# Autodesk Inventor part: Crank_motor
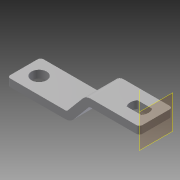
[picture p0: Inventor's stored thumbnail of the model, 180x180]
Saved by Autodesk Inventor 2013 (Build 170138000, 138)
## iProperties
Created: 2006-03
Part Number: Crank_motor
Document SubType Name: Modeling
Designer: debonom
Material: Stainless Steel, 440C
Mass: 73.5464 g
Surface Area: 52.6545 cm^2
Volume: 9.48986 cm^3
Density: 7.75 g/cm^3
Author: debonom
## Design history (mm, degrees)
sketch "Sketch1"
  geometry: L1 (0, 0)-(-34.15, 0); L2 (0, 0)-(12.586, -15); L3 (12.586, -15)-(53.05, -15)
  constraints: 6 end point, 1 horizontal, 1 parallel
  dimensions: "d0" = 130 deg angle of L2 L1; "d1" = 87.2 horizontal distance of L3.end L1.end; "d2" = 34.15 distance of L1.start L1.end; "d3" = 15 distance between parallel lines of L3 L1
workplane "Work Plane1"
sketch "Sketch2"
  geometry: L1 (-11, 2.5)-(11, 2.5); L2 (11, 2.5)-(11, -2.5); L3 (11, -2.5)-(-11, -2.5); L4 (-11, -2.5)-(-11, 2.5); L5 (-11, 2.5)-(11, -2.5); 2 further points
  constraints: 10 end point, 2 parallel, 1 coincident, 1 horizontal, 1 midpoint, 1 perpendicular
  dimensions: "d4" = 22 distance of L1.start L1.end; "d5" = 5 distance of L3.end L1.start
sweep "Sweep1" sketch "Sketch2" dims "d6" = 0
fillet "Fillet1" dims "d7" = 7
fillet "Fillet2" dims "d8" = 2
sketch "Sketch4"
  geometry: L1 (-104.64, 11)-(17.44, 11) reference; L2 (0, 26.4)-(0, -4.4) reference; L3 (-15.823, 7.425)-(-6.178, 7.425); L4 (-6.178, 7.425)-(-6.178, 14.575); L5 (-6.178, 14.575)-(-15.823, 14.575); L6 (-15.823, 14.575)-(-15.823, 7.425); L7 (-15.823, 7.425)-(-6.178, 14.575); A1 r 6 centre (-10.997, 11) between (-6.178, 7.425) and (-6.178, 14.575); A2 r 6 centre (-11.004, 11) between (-15.823, 14.575) and (-15.823, 7.425); 2 further points
  constraints: 10 end point, 4 point on circle, 3 point on line, 2 centre point, 2 parallel, 1 equal radius, 1 horizontal, 1 midpoint, 1 perpendicular
  dimensions: "d18" = 9.645 distance of L3.start L3.end; "d19" = 7.15 distance of L5.end L3.start; "d20" = 6.178 distance from line of L3.end L2; "d21" = 6 radius of A2
extrude "Extrusion3" cut sketch "Sketch4" stored distance "d22" = 10; taper "d23" = 0 deg
sketch "Sketch3"
  geometry: L1 (-17.44, 11)-(104.64, 11) reference; L2 (0, 22)-(0, 0) reference; C1 r 5 at (10, 11); 1 further point
  constraints: 1 centre point, 1 point on line
  dimensions: "d9" = 10 distance from line of C1.centre L2; "d10" = 10 diameter of C1
extrude "Extrusion1" cut sketch "Sketch3" stored distance "d11" = 10; taper "d12" = 0 deg
fillet "Fillet3" dims "d17" = 2
workaxis "Work Axis2"
  workplane "Work Plane3"
body "Solid1"
